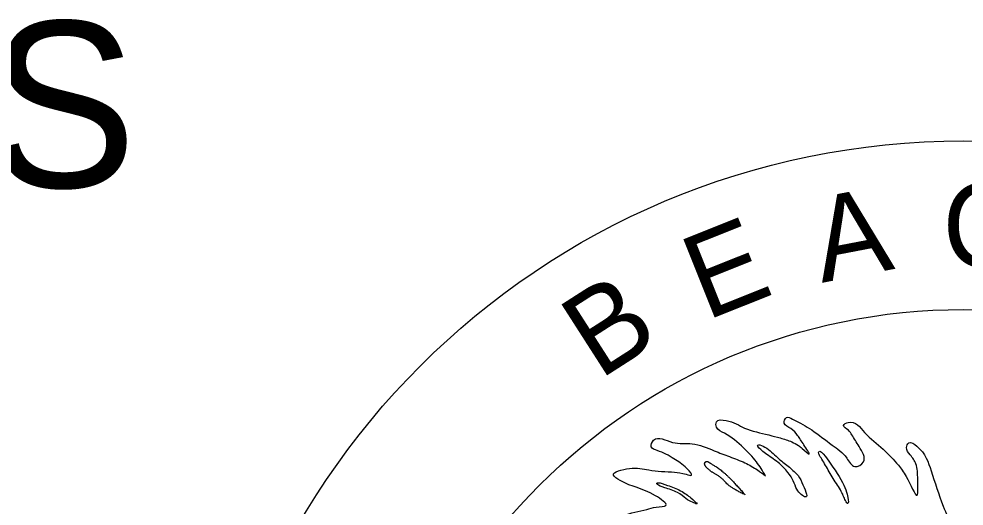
# Model space of a CAD drawing. Extents: x 801329 to 1085229, y 842463 to 1044570.
# Drawn here: x 918418 to 938507, y 934394 to 944753 of the extents above; entities that cross this region are included whole.
import ezdxf

# ---------------------------------------------------------------- set-up
doc = ezdxf.new("R2010")
doc.units = 0
doc.layers.add('Default', color=7, linetype='Continuous')
doc.layers.add('TextLabel', color=7, linetype='Continuous')

msp = doc.modelspace()

# ---------------------------------------------------------------- linework, layer by layer
at = {"layer": 'Default'}
for radius in [16331, 12746]:
    msp.add_circle((938498, 925828), radius, dxfattribs=at)
for points in [[(934285, 935040), (934093, 935338), (933820, 935630), (933414, 935944), (933247, 936075), (933242, 936183), (933450, 936214), (933843, 936054), (934355, 935907), (934600, 935842), (934845, 935759), (934986, 935682), (935065, 935621), (935214, 935501), (935104, 935694), (934969, 935897), (934823, 936043), (934685, 936156), (934730, 936275), (934860, 936245), (935268, 936013), (935703, 935691), (936012, 935415), (936186, 935234), (936368, 935334), (936274, 935660), (936124, 935909), (936047, 936005), (935946, 936108), (936045, 936174), (936393, 935960), (936788, 935602), (937109, 935261), (937277, 935022), (937508, 934626), (937522, 934957), (937482, 935291), (937360, 935484), (937283, 935637), (937332, 935739), (937505, 935669), (937806, 935144), (938064, 934393), (938238, 933942), (938382, 933347), (938475, 932848), (938522, 932521), (938521, 932302), (938545, 932155), (938651, 932285), (938719, 932858), (938874, 933648), (938982, 934146), (939107, 934752), (939198, 935261), (939270, 935754), (939340, 936180), (939331, 936572), (939363, 936867), (939430, 937016), (939516, 936977), (939559, 936730), (939629, 936270), (939710, 935886), (939783, 935783), (939783, 936049), (939729, 936646), (939715, 936905), (939799, 937010), (939912, 936914), (939958, 936703), (940023, 936632), (939997, 937013), (940047, 937283), (939985, 937628), (939929, 937828), (940101, 937860), (940258, 937628), (940481, 937030), (940684, 936612), (940798, 936365), (940801, 936135), (940822, 936510), (940815, 937042), (940808, 937578), (940743, 937894), (940738, 938360)], [(934717, 932599), (934672, 932699), (934792, 932851), (934973, 933063), (935061, 933193), (934953, 933177), (934809, 933201), (934597, 933223), (934368, 933162), (933641, 932760), (933540, 932543), (933453, 932351), (933368, 932217), (933287, 932115), (933158, 932138), (933209, 932341), (933397, 932742), (933637, 933109), (933774, 933316), (933509, 933280), (933272, 933273), (932919, 933110), (932695, 932992), (932406, 932822), (932171, 932639), (932017, 932400), (931879, 932186), (931775, 932213), (931801, 932382), (931952, 932679), (932087, 933059), (932050, 933138), (931557, 932976), (931165, 932791), (930818, 932624), (930630, 932485), (930499, 932332), (930315, 932423), (930537, 932761), (930766, 933095), (931028, 933383), (930787, 933433), (930489, 933397), (930221, 933285), (929911, 933169), (929765, 933081), (929638, 933159), (929786, 933391), (930327, 933718), (930765, 933969), (931251, 934195), (931762, 934324), (931962, 934370), (932170, 934409), (931945, 934615), (931194, 934939), (931057, 935052), (931392, 935193), (931805, 935163), (932078, 935131), (932351, 935117), (932603, 935070), (932715, 935050), (932620, 935189), (932341, 935397), (932171, 935499), (931986, 935576), (931856, 935657), (931908, 935794), (932307, 935749), (932728, 935719), (933196, 935571), (933521, 935446), (933849, 935313), (934113, 935162), (934287, 935039)]]:
    msp.add_spline(points, degree=3, dxfattribs=at)
for points, degree in [([(935135, 934588), (935157, 934585), (935180, 934619), (935080, 934851), (934997, 935050), (934798, 935216), (934566, 935398), (934450, 935514), (934317, 935630), (934151, 935713), (934085, 935680), (934267, 935514), (934566, 935332), (934781, 935100), (934881, 934934), (934947, 934735), (935047, 934635), (935113, 934591), (935135, 934588)], 3), ([(935442, 935559), (935423, 935559), (935379, 935547), (935545, 935299), (935694, 935017), (935893, 934735), (935993, 934486), (936042, 934419), (936059, 934536), (935943, 934917), (935495, 935547), (935462, 935559), (935442, 935559)], 3), ([(933852, 934635), (933603, 934917), (933321, 935183), (933122, 935299), (933023, 935365), (932973, 935266), (933139, 935116), (933354, 935000), (933537, 934784), (933852, 934635)], 2), ([(932817, 934441), (932834, 934436), (932840, 934442), (932713, 934560), (932496, 934732), (932188, 934840), (931980, 934913), (931962, 934858), (932116, 934786), (932442, 934696), (932596, 934542), (932741, 934469), (932801, 934445), (932817, 934441)], 3)]:
    msp.add_open_spline(points, degree=degree, dxfattribs=at)

# ---------------------------------------------------------------- texts
for s, rotation, p in [('C', 0.0002, (938046, 939469)), ('A', 10.8913, (935484, 939140)), ('E', 21.7824, (933023, 938330)), ('B', 32.6734, (930753, 937067))]:
    msp.add_text(s, height=1792, rotation=rotation, dxfattribs=at).set_placement(p)
at = {"layer": 'TextLabel'}
msp.add_text('GREGG K. WEISS', height=3531.23, rotation=360, dxfattribs=at).set_placement((881043, 941169))

doc.saveas('drawing.dxf')
